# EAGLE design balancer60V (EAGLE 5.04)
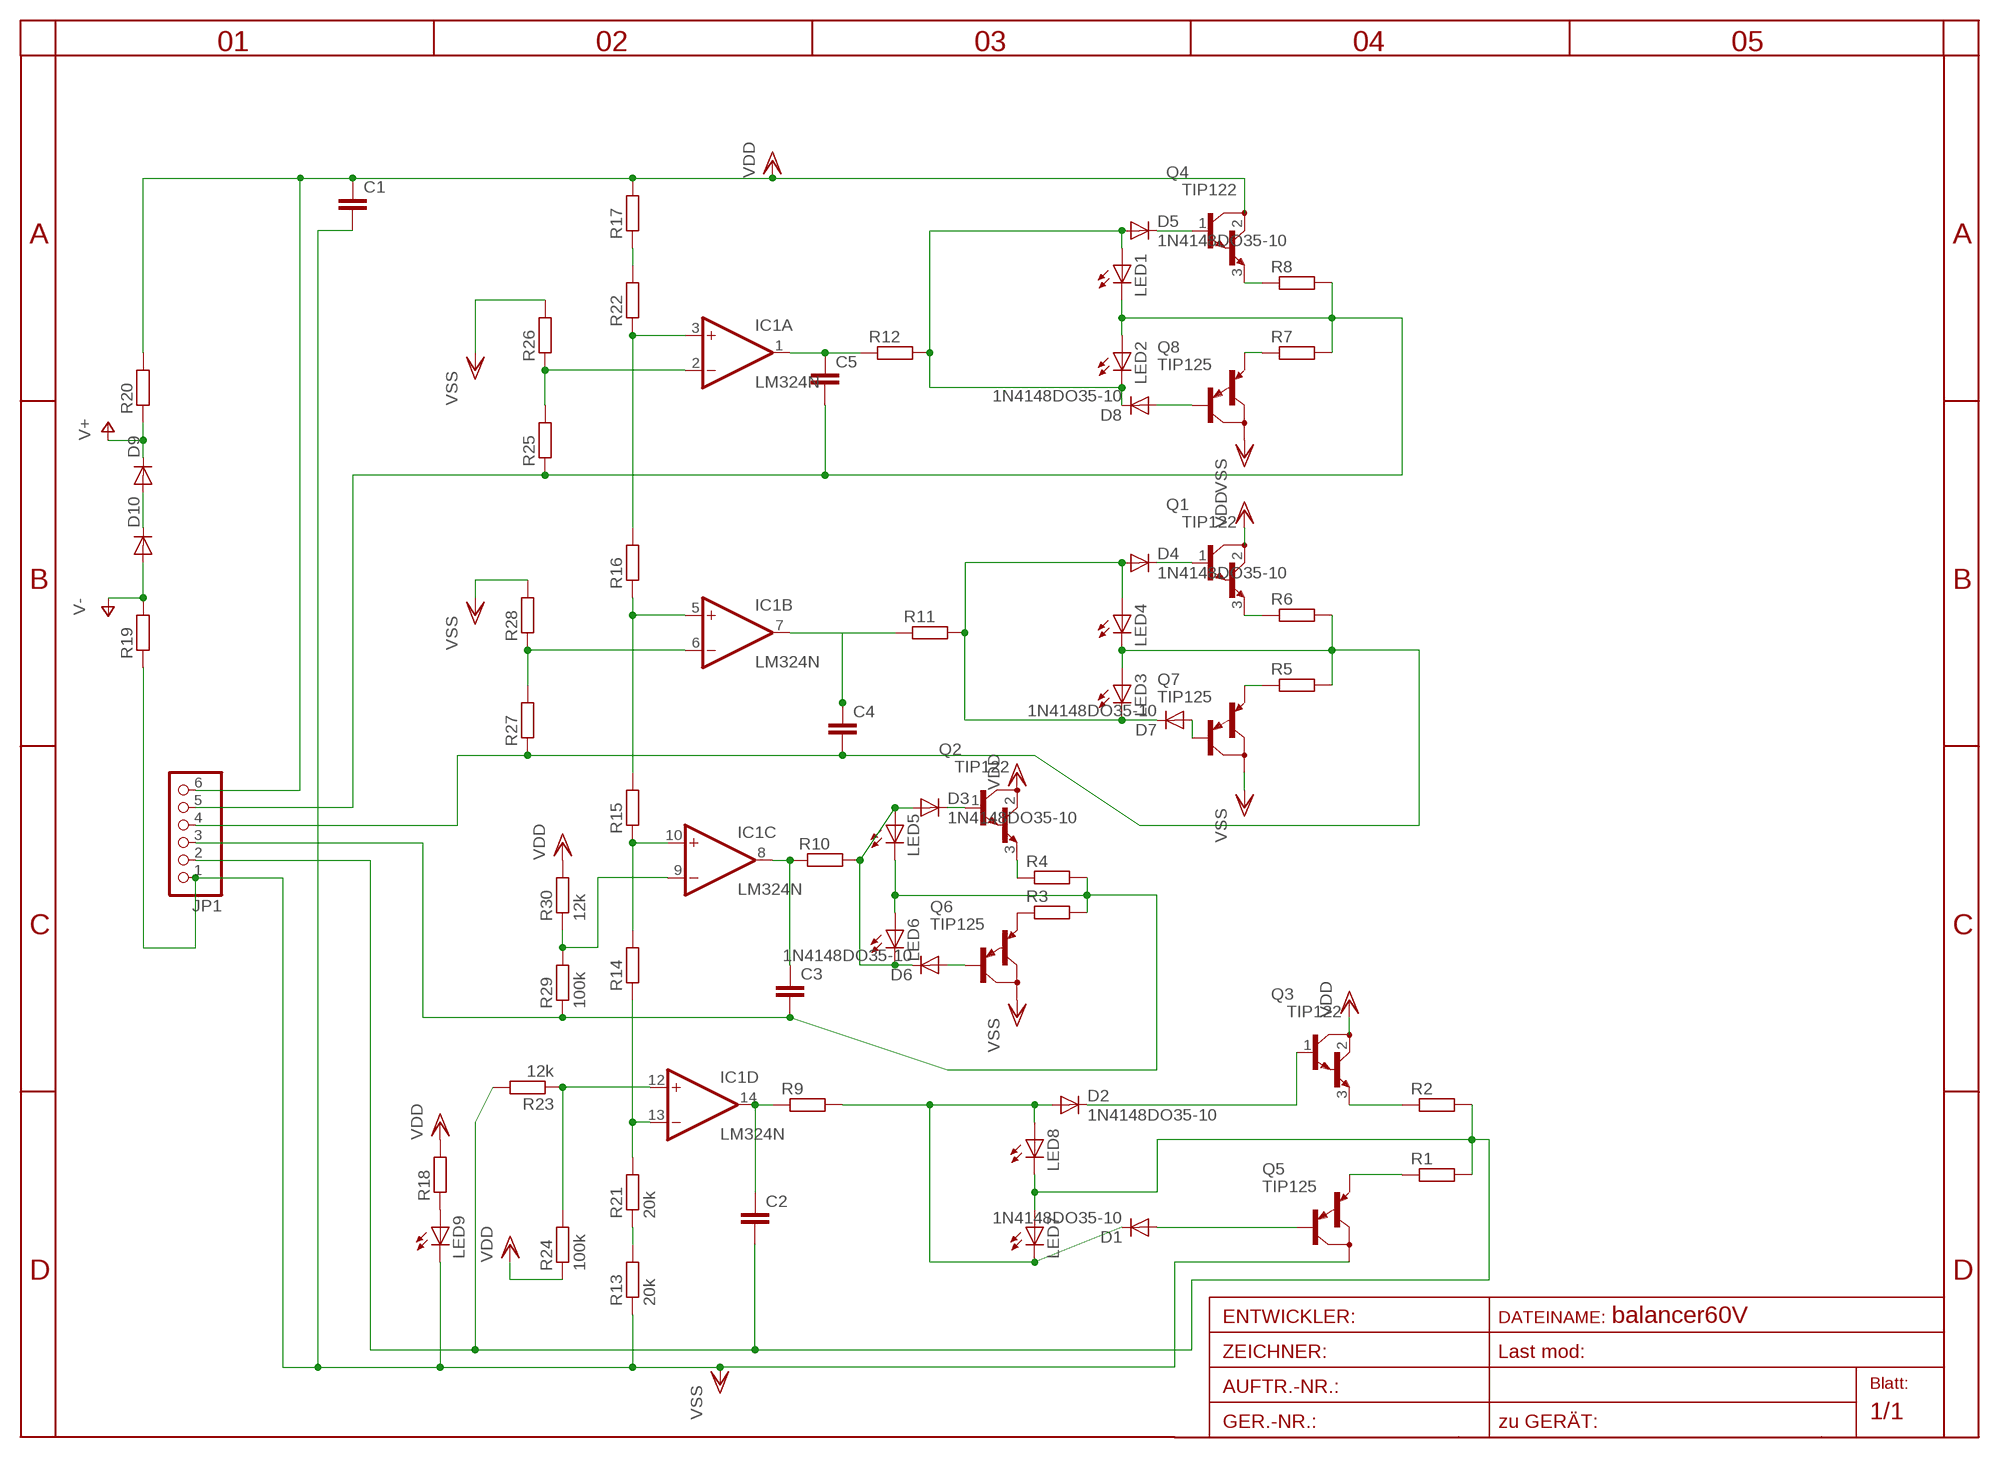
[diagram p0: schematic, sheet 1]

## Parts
C1  C-EU025-024X044  [C025-024X044]
C2  C-EU025-024X044  [C025-024X044]
C3  C-EU025-024X044  [C025-024X044]
C4  C-EU025-024X044  [C025-024X044]
C5  C-EU025-024X044  [C025-024X044]
D1  1N4148DO35-10  [DO35-10]
D2  1N4148DO35-10  [DO35-10]
D3  1N4148DO35-10  [DO35-10]
D4  1N4148DO35-10  [DO35-10]
D5  1N4148DO35-10  [DO35-10]
D6  1N4148DO35-10  [DO35-10]
D7  1N4148DO35-10  [DO35-10]
D8  1N4148DO35-10  [DO35-10]
D9  DIODE-D-10  [D-10]
D10  DIODE-D-10  [D-10]
IC1  LM324N  [DIL14]
JP1  PINHD-1X6  [1X06]
LED1  LED3MM  [LED3MM]
LED2  LED3MM  [LED3MM]
LED3  LED3MM  [LED3MM]
LED4  LED3MM  [LED3MM]
LED5  LED3MM  [LED3MM]
LED6  LED3MM  [LED3MM]
LED7  LED3MM  [LED3MM]
LED8  LED3MM  [LED3MM]
LED9  LED3MM  [LED3MM]
Q1  TIP122  [TO220]
Q2  TIP122  [TO220]
Q3  TIP122  [TO220]
Q4  TIP122  [TO220]
Q5  TIP125  [TO220]
Q6  TIP125  [TO220]
Q7  TIP125  [TO220]
Q8  TIP125  [TO220]
R1  R-EU_0207/10  [0207/10]
R2  R-EU_0207/10  [0207/10]
R3  R-EU_0207/10  [0207/10]
R4  R-EU_0207/10  [0207/10]
R5  R-EU_0207/10  [0207/10]
R6  R-EU_0207/10  [0207/10]
R7  R-EU_0207/10  [0207/10]
R8  R-EU_0207/10  [0207/10]
R9  R-EU_0207/10  [0207/10]
R10  R-EU_0207/10  [0207/10]
R11  R-EU_0204/5  [0204/5]
R12  R-EU_0207/10  [0207/10]
R13  20k  R-EU_0204/5  [0204/5]
R14  R-EU_0204/5  [0204/5]
R15  R-EU_0204/5  [0204/5]
R16  R-EU_0204/5  [0204/5]
R17  R-EU_0204/5  [0204/5]
R18  R-EU_0204/5  [0204/5]
R19  R-EU_0204/5  [0204/5]
R20  R-EU_0204/5  [0204/5]
R21  20k  R-EU_0204/5  [0204/5]
R22  R-EU_0204/5  [0204/5]
R23  12k  R-EU_0204/5  [0204/5]
R24  100k  R-EU_0204/5  [0204/5]
R25  R-EU_0204/5  [0204/5]
R26  R-EU_0204/5  [0204/5]
R27  R-EU_0204/5  [0204/5]
R28  R-EU_0204/5  [0204/5]
R29  100k  R-EU_0204/5  [0204/5]
R30  12k  R-EU_0204/5  [0204/5]

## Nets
N$1: D1.C D2.A LED7.K(C) LED8.A R9.2
N$2: C2.2 JP1.2 LED7.A LED8.K(C) R1.2 R2.2 R23.2
N$3: D3.C Q2.1(B)
N$4: D4.C Q1.1(B)
N$5: D5.C Q4.1(B)
N$6: D6.A Q6.1(B)
N$7: D7.A Q7.1(B)
N$8: D8.A Q8.1(B)
N$9: D2.C Q3.1(B)
N$10: D3.A D6.C LED5.A LED6.K(C) R10.2
N$11: D4.A D7.C LED3.K(C) LED4.A R11.2
N$12: D5.A D8.C LED1.A LED2.K(C) R12.2
N$13: Q3.3(E) R2.1
N$14: Q7.3(E) R5.1
N$15: Q1.3(E) R6.1
N$16: Q6.3(E) R3.1
N$17: Q2.3(E) R4.1
N$18: Q4.3(E) R8.1
N$19: Q8.3(E) R7.1
N$20: C5.1 IC1.1(A:OUT) R12.1
N$21: C4.1 IC1.7(B:OUT) R11.1
N$23: R17.1 R22.2
N$24: C3.1 IC1.8(C:OUT) R10.1
N$25: C2.1 IC1.14(D:OUT) R9.1
N$26: IC1.10(C:+IN) R14.2 R15.1
N$28: IC1.13(D:-IN) R14.1 R21.2
N$29: R13.2 R21.1
N$30: C5.2 JP1.5 LED1.K(C) LED2.A R7.2 R8.2 R25.1
N$32: IC1.3(A:+IN) R16.2 R22.1
N$33: C3.2 JP1.3 LED5.K(C) LED6.A R3.2 R4.2 R29.1
N$34: LED9.A R18.1
N$35: D9.A D10.C
N$36: IC1.5(B:+IN) R15.2 R16.1
N$37: IC1.12(D:+IN) R23.1 R24.2
N$38: C4.2 JP1.4 LED3.A LED4.K(C) R5.2 R6.2 R27.1
N$40: IC1.2(A:-IN) R25.2 R26.1
N$41: IC1.6(B:-IN) R27.2 R28.1
N$42: IC1.9(C:-IN) R29.2 R30.1
N$43: Q5.3(E) R1.1
N$44: D1.A Q5.1(B)
V+: D9.C R20.1
V-: D10.A R19.2
VDD: C1.1 JP1.6 Q1.2(C) Q2.2(C) Q3.2(C) Q4.2(C) R17.2 R18.2 R20.2 R24.1 R30.2
VSS: C1.2 JP1.1 LED9.K(C) Q5.2(C) Q6.2(C) Q7.2(C) Q8.2(C) R13.1 R19.1 R26.2 R28.2

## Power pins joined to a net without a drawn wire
V+: IC1.4(P:V+)
V-: IC1.11(P:V-)

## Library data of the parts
C1-C5 = rcl-2:C-EU: CAPACITOR, European symbol
D1-D8 = diode-1:1N4148: DIODE
D9 D10 = diode-1:DIODE-: DIODE
IC1 = linear:LM324: OP AMP
JP1 = pinhead:PINHD-1X6: PIN HEADER
LED1-LED9 = led:LED: LED
Q1-Q4 = transistor-npn:TIP122*: NPN Darlington Transistor
Q5-Q8 = transistor-pnp:TIP125: PNP Transistor
R1-R30 = rcl-2:R-EU_: RESISTOR, European symbol

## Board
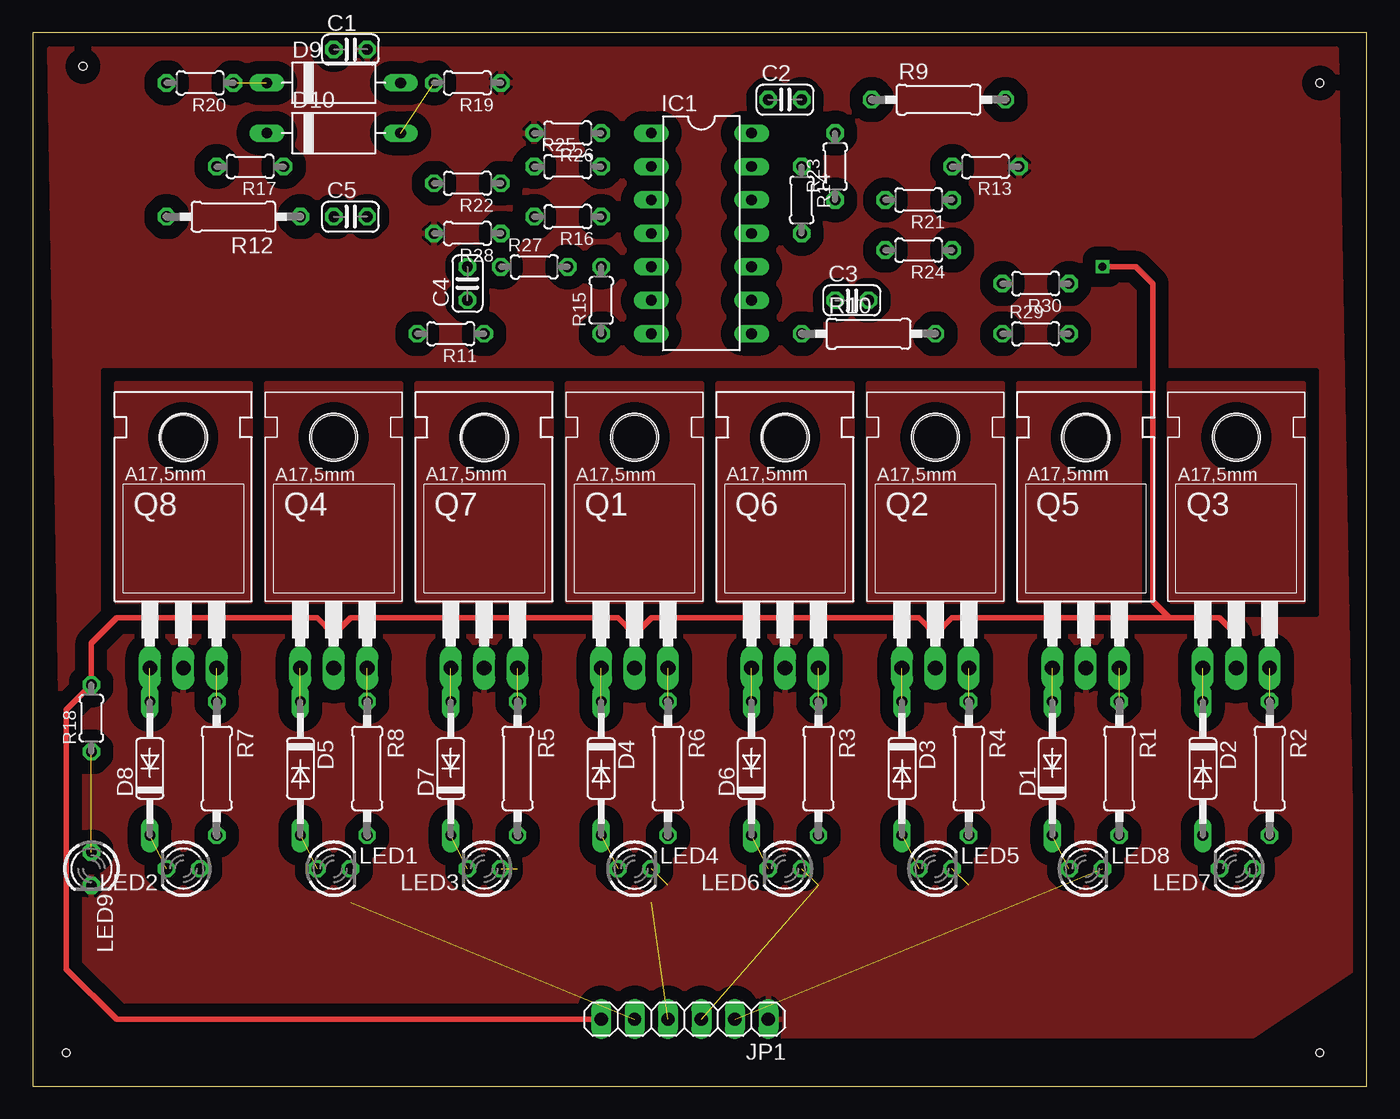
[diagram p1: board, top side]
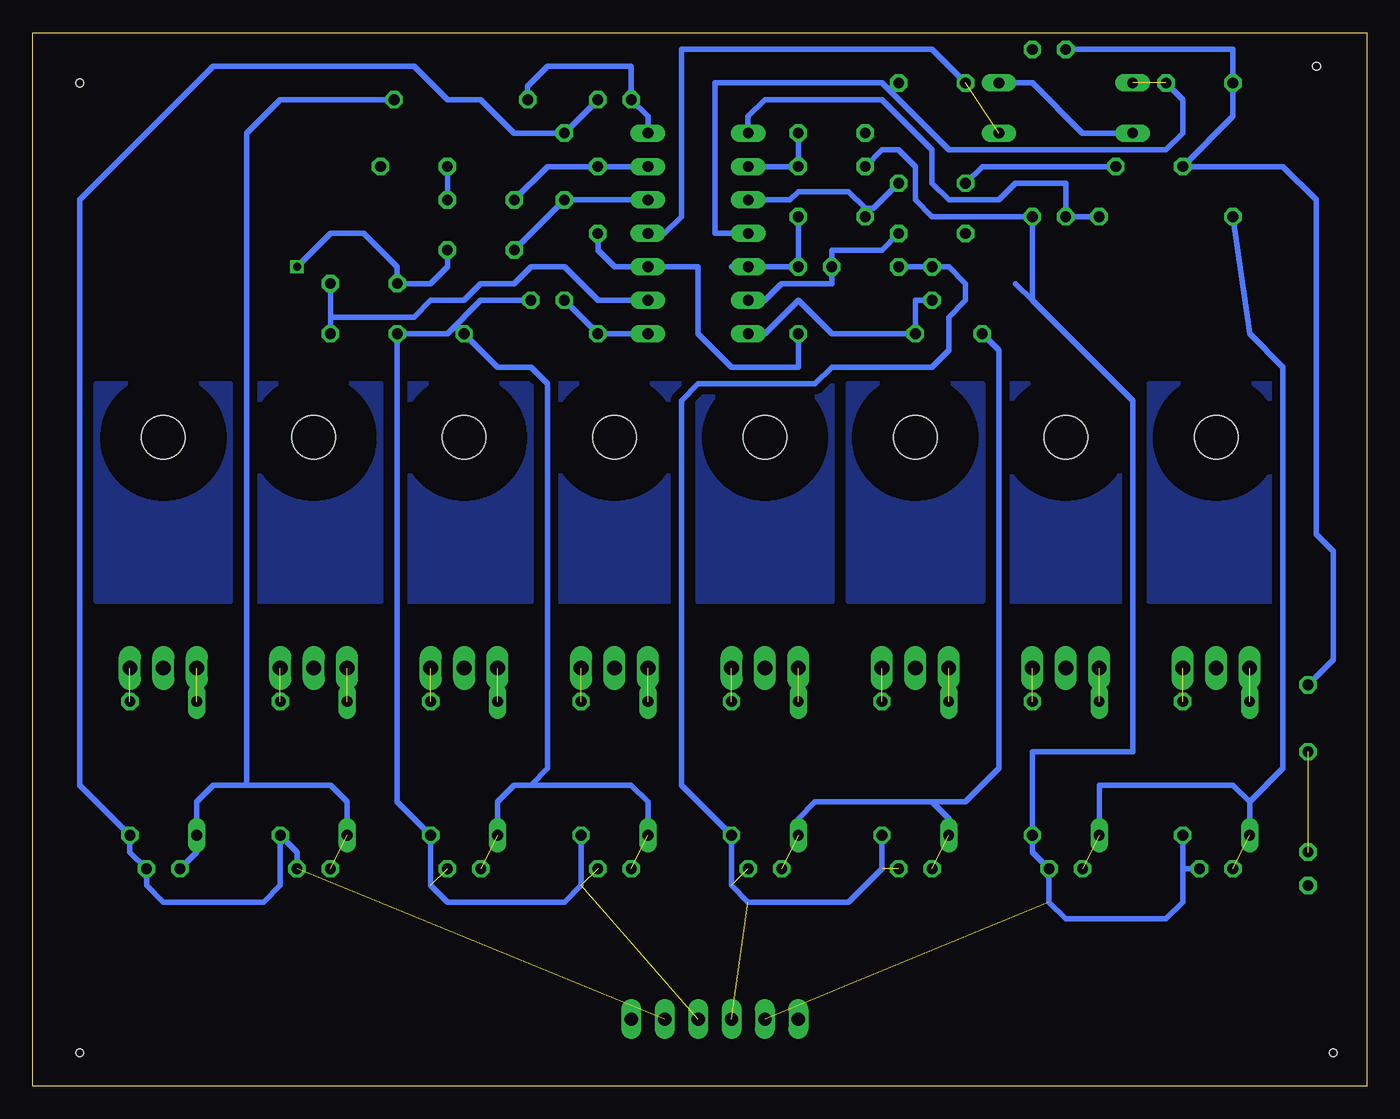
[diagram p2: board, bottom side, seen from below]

Size 101.35 x 80 mm. Coordinates in mm from the lower left corner, seen from the top.
Outline: 0,0 101.35,0 101.35,80 0,80 0,0
Copper layers (1*16): Top 0.035mm / dielectric 1.5mm / Bottom 0.035mm
Design rules "default": minimum track width 10mil, minimum drill 24mil, track to track 8mil, track to pad 8mil, pad to pad 8mil, via to via 8mil, smd to smd 8mil, copper to edge 40mil, drill to drill 8mil, minimum pad ring 10mil, minimum via ring 8mil, stop-mask expansion 4mil, vias tented up to drill 0mil, thermal gap 10mil
Holes 0.6 mm at 2.54,2.54 97.79,2.54 97.79,76.2 3.81,77.47

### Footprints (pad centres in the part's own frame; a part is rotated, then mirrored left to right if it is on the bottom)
C025-024X044 = drill 0.813 octagon: 1 -1.27,0; 2 1.27,0
DO35-10 = drill 0.813 long: A 5.08,0; C -5.08,0
D-10 = drill 0.813 long: A 5.08,0; C -5.08,0
DIL14 = drill 0.813 long: 1 -7.62,-3.81; 2 -5.08,-3.81; 3 -2.54,-3.81; 4 0,-3.81; 5 2.54,-3.81; 6 5.08,-3.81; 7 7.62,-3.81; 8 7.62,3.81; 9 5.08,3.81; 10 2.54,3.81; 11 0,3.81; 12 -2.54,3.81; 13 -5.08,3.81; 14 -7.62,3.81
1X06 = drill 1.016 long: 1 -6.35,0; 2 -3.81,0; 3 -1.27,0; 4 1.27,0; 5 3.81,0; 6 6.35,0
LED3MM = drill 0.813 octagon: A -1.27,0; K 1.27,0
TO220 = drill 1.118 long: 1 -2.54,-6.35; 2 0,-6.35; 3 2.54,-6.35 | hole 3.302: 0,11.176
0207/10 = drill 0.813 octagon: 1 -5.08,0; 2 5.08,0
0204/5 = drill 0.813 octagon: 1 -2.54,0; 2 2.54,0

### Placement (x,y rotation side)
C1  24.13,78.74 0 top
C2  57.15,74.93 0 top
C3  62.23,59.69 0 top
C4  33.02,60.96 90 top
C5  24.13,66.04 0 top
D1  77.47,24.13 90 top
D2  88.9,24.13 270 top
D3  66.04,24.13 270 top
D4  43.18,24.13 270 top
D5  20.32,24.13 270 top
D6  54.61,24.13 90 top
D7  31.75,24.13 90 top
D8  8.89,24.13 90 top
D9  22.86,76.2 0 top
D10  22.86,72.39 0 top
IC1  50.8,64.77 270 top
JP1  49.53,5.08 180 top
LED1  22.86,16.51 0 top
LED2  11.43,16.51 180 top
LED3  34.29,16.51 180 top
LED4  45.72,16.51 0 top
LED5  68.58,16.51 0 top
LED6  57.15,16.51 180 top
LED7  91.44,16.51 180 top
LED8  80.01,16.51 0 top
LED9  4.45,16.51 270 top
Q1  45.72,38.1 0 top
Q2  68.58,38.1 0 top
Q3  91.44,38.1 0 top
Q4  22.86,38.1 0 top
Q5  80.01,38.1 0 top
Q6  57.15,38.1 0 top
Q7  34.29,38.1 0 top
Q8  11.43,38.1 0 top
R1  82.55,24.13 270 top
R2  93.98,24.13 270 top
R3  59.69,24.13 270 top
R4  71.12,24.13 270 top
R5  36.83,24.13 270 top
R6  48.26,24.13 270 top
R7  13.97,24.13 270 top
R8  25.4,24.13 270 top
R9  68.82,74.93 0 top
R10  63.5,57.15 0 top
R11  31.75,57.15 180 top
R12  15.24,66.04 180 top
R13  72.39,69.85 180 top
R14  58.42,67.31 270 top
R15  43.18,59.69 90 top
R16  40.64,66.04 180 top
R17  16.51,69.85 180 top
R18  4.45,27.94 90 top
R19  33.02,76.2 180 top
R20  12.7,76.2 180 top
R21  67.31,67.31 180 top
R22  33.02,68.58 180 top
R23  60.96,69.85 90 top
R24  67.31,63.5 180 top
R25  40.64,69.85 0 top
R26  40.64,72.39 180 top
R27  38.1,62.23 0 top
R28  33.02,64.77 180 top
R29  76.2,57.15 0 top
R30  76.2,60.96 180 top

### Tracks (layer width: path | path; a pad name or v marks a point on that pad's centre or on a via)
N$1  (1 unrouted)
  Bottom 0.406: D1.C 77.47,21.59 78.74,22.86 85.09,22.86 | 85.09,22.86 87.63,22.86 88.9,21.59 D2.A 88.9,17.78 LED7.K | R9.2 82.55,74.93 85.09,72.39 85.09,22.86
N$2  (1 unrouted)
  Bottom 0.406: LED8.K 81.28,17.78 R1.2 82.55,15.24 83.82,13.97 91.44,13.97 92.71,15.24 LED7.A 93.98,17.78 R2.2 97.79,22.86 97.79,67.31 87.63,77.47 72.39,77.47 69.85,74.93 67.31,74.93 64.77,72.39 R23.2 C2.2
N$3  (1 unrouted)
N$4  (1 unrouted)
N$5  (1 unrouted)
N$6  (1 unrouted)
N$7  (1 unrouted)
N$8  (1 unrouted)
N$9  (1 unrouted)
N$10  (2 unrouted)
  Bottom 0.406: D6.C 54.61,21.59 55.88,22.86 64.77,22.86 | 64.77,22.86 66.04,21.59 D3.A | 64.77,22.86 63.5,22.86 62.23,24.13 62.23,53.34 63.5,54.61 66.04,54.61 R10.2
N$11  (2 unrouted)
  Bottom 0.406: D4.A 43.18,20.32 41.91,21.59 33.02,21.59 | 33.02,21.59 31.75,20.32 D7.C | 33.02,21.59 30.48,21.59 27.94,24.13 27.94,55.88 R11.2
N$12  (2 unrouted)
  Bottom 0.406: D8.C 8.89,21.59 | 8.89,21.59 10.16,22.86 20.32,22.86 D5.A | R12.2 8.89,57.15 6.35,54.61 6.35,24.13 8.89,21.59
N$13  (1 unrouted)
N$14  (1 unrouted)
N$15  (1 unrouted)
N$16  (1 unrouted)
N$17  (1 unrouted)
N$18  (1 unrouted)
N$19  (1 unrouted)
N$20
  Bottom 0.406: R12.1 C5.1 22.86,68.58 26.67,68.58 27.94,67.31 31.75,67.31 33.02,68.58 33.02,71.12 36.83,74.93 45.72,74.93 46.99,73.66 IC1.1
N$21
  Bottom 0.406: IC1.7 45.72,57.15 43.18,59.69 40.64,57.15 R11.1 34.29,59.69 C4.1
N$23
  Bottom 0.406: R22.2 29.21,69.85 R17.1
N$24
  Bottom 0.406: IC1.8 R10.1 C3.1
N$25
  Bottom 0.406: R9.1 63.74,75.96 62.23,77.47 55.88,77.47 C2.1 54.61,73.66 IC1.14
N$26
  Bottom 0.406: R14.2 58.42,63.5 57.15,62.23 IC1.10 50.8,62.23 50.8,57.15 48.26,54.61 43.18,54.61 R15.1
N$28
  Bottom 0.406: R21.2 62.23,69.85 R14.1 IC1.13
N$29
  Bottom 0.406: R21.1 R13.2
N$30  (1 unrouted)
  Bottom 0.406: 13.97,16.51 13.97,13.97 15.24,12.7 22.86,12.7 24.13,13.97 LED1.K 25.4,17.78 R8.2 25.4,25.4 17.78,25.4 17.78,52.07 25.4,59.69 | 13.97,16.51 R7.2 | 13.97,16.51 LED2.A | 25.4,59.69 26.67,60.96 | 25.4,59.69 C5.2 33.02,66.04 34.29,67.31 34.29,69.85 35.56,71.12 36.83,71.12 R25.1
N$31
  pour Bottom (isolate 0.61, rank 4): 6.35,53.34 16.51,53.34 16.51,36.83 6.35,36.83
  pour Top (isolate 0.61, rank 4): 6.35,53.34 16.51,53.34 16.51,36.83 6.35,36.83
  pour Top (isolate 0.61, rank 4): 17.78,53.34 27.94,53.34 27.94,36.83 17.78,36.83
  pour Top (isolate 0.61, rank 4): 29.21,53.34 39.37,53.34 39.37,36.83 29.21,36.83
  pour Top (isolate 0.61, rank 4): 40.64,53.34 50.8,53.34 50.8,36.83 40.64,36.83
  pour Top (isolate 0.61, rank 4): 52.07,53.34 62.23,53.34 62.23,36.83 52.07,36.83
  pour Top (isolate 0.61, rank 4): 63.5,53.34 73.66,53.34 73.66,36.83 63.5,36.83
  pour Top (isolate 0.61, rank 4): 74.93,53.34 85.09,53.34 85.09,36.83 74.93,36.83
  pour Top (isolate 0.61, rank 4): 86.36,53.34 96.52,53.34 96.52,36.83 86.36,36.83
  pour Bottom (isolate 0.61, rank 4): 17.78,53.34 27.94,53.34 27.94,36.83 17.78,36.83
  pour Bottom (isolate 0.61, rank 4): 29.21,53.34 39.37,53.34 39.37,36.83 29.21,36.83
  pour Bottom (isolate 0.61, rank 4): 40.64,53.34 50.8,53.34 50.8,36.83 40.64,36.83
  pour Bottom (isolate 0.61, rank 4): 52.07,53.34 62.23,53.34 62.23,36.83 52.07,36.83
  pour Bottom (isolate 0.61, rank 4): 63.5,53.34 73.66,53.34 73.66,36.83 63.5,36.83
  pour Bottom (isolate 0.61, rank 4): 74.93,53.34 85.09,53.34 85.09,36.83 74.93,36.83
  pour Bottom (isolate 0.61, rank 4): 86.36,53.34 96.52,53.34 96.52,36.83 86.36,36.83
N$32
  Bottom 0.406: IC1.3 43.81,67.31 43.18,67.94 39.37,67.94 38.1,66.67 | 38.1,66.67 R16.2 | 38.1,66.67 37.47,66.67 R22.1
N$33  (3 unrouted)
  Bottom 0.406: R3.2 59.69,15.24 60.96,13.97 69.85,13.97 71.12,15.24 R4.2 73.66,21.59 R29.1 69.85,57.15 67.31,59.69 C3.2
N$34  (1 unrouted)
N$35
  Bottom 0.406: D10.C 21.59,72.39 25.4,76.2 D9.A
N$36
  Bottom 0.406: R16.1 R15.2 IC1.5 48.26,62.23
N$37
  Bottom 0.406: IC1.12 R23.1 R24.2
N$38  (3 unrouted)
  Bottom 0.406: R5.2 36.83,16.51 39.37,13.97 46.99,13.97 48.26,15.24 R6.2 52.07,22.86 52.07,52.07 50.8,53.34 41.91,53.34 40.64,54.61 33.02,54.61 31.75,55.88 31.75,58.42 30.48,59.69 30.48,60.96 31.75,62.23 C4.2 R27.1
N$40
  Bottom 0.406: IC1.2 R25.2 R26.1
N$41
  Bottom 0.406: IC1.6 45.72,59.69 44.45,60.96 40.64,60.96 R27.2 40.64,63.5 36.83,63.5 R28.1
N$42
  Bottom 0.406: 78.74,58.42 R29.2 | 78.74,58.42 R30.1 | IC1.9 58.42,59.69 60.96,62.23 63.5,62.23 64.77,60.96 67.31,60.96 68.58,59.69 71.12,59.69 72.39,58.42 78.74,58.42
N$43  (1 unrouted)
N$44  (1 unrouted)
V+  (1 unrouted)
  Bottom 0.406: IC1.4 49.53,64.77 49.53,76.2 36.83,76.2 31.75,71.12 15.24,71.12 13.97,72.39 13.97,74.93 R20.1
V-  (1 unrouted)
  Bottom 0.406: IC1.11 53.34,64.77 52.07,66.04 52.07,78.74 33.02,78.74 R19.2
VDD  (via drill 0.6)
  Top 0.406: 22.86,34.29 21.59,35.56 6.35,35.56 4.45,33.66 R18.2 2.54,28.57 2.54,8.89 6.35,5.08 JP1.6 | 22.86,34.29 Q4.2 | 22.86,34.29 24.13,35.56 44.45,35.56 45.72,34.29 | 45.72,34.29 Q1.2 | 45.72,34.29 46.99,35.56 67.31,35.56 68.58,34.29 | 68.58,34.29 Q2.2 | 68.58,34.29 69.85,35.56 86.36,35.56 | v81.28,62.23 83.82,62.23 85.09,60.96 85.09,36.83 86.36,35.56 | 86.36,35.56 90.17,35.56 91.44,34.29 Q3.2
  Bottom 0.406: R24.1 69.85,62.23 71.12,60.96 R30.2 73.66,62.23 76.2,64.77 78.74,64.77 v81.28,62.23 | C1.1 10.16,78.74 R20.2 10.16,73.66 R17.2 6.35,69.85 3.81,67.31 3.81,41.91 2.54,40.64 2.54,32.38 R18.2
VSS
  pour Top (isolate 1.016, rank 5): 1.27,78.74 99.06,78.74 100.33,8.89 92.71,3.81 3.81,3.81 2.54,5.08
